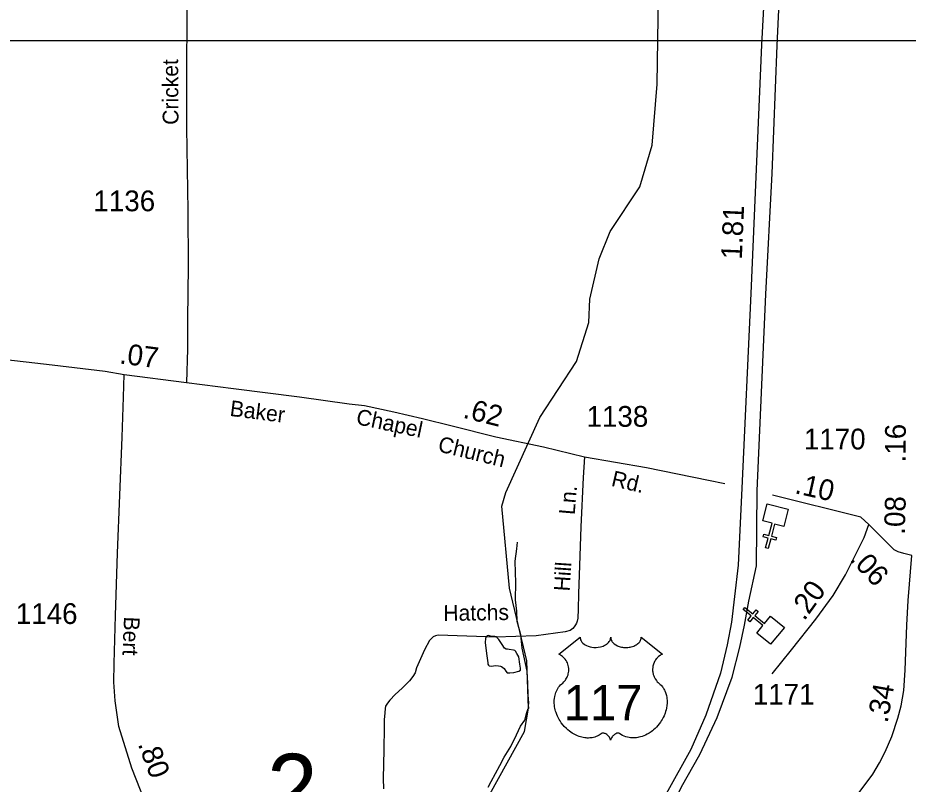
# Model space of a CAD drawing. Extents: x 2206922 to 2357709, y 510027 to 673830.
# Drawn here: x 2276310 to 2281670, y 535777 to 540388 of the extents above; entities that cross this region are included whole.
import ezdxf

# ---------------------------------------------------------------- set-up
doc = ezdxf.new("R2010")
doc.units = 0
for name, color, linetype in [('Exist Cultural Church CELL', 7, 'Continuous'), ('Exist Hydrographic Creek Single Shore', 7, 'Continuous'), ('Exist Hydrographic Misc Water Feature', 7, 'Continuous'), ('Exist Road Non-System Type 51', 7, 'Continuous'), ('Exist Road Non-System Type 51 Label', 7, 'Continuous'), ('Exist Road Primary US Attributed', 7, 'Continuous'), ('Exist Road Primary US Divided Attributed', 7, 'Continuous'), ('Exist Road Primary US Mileage Hundredths English Label', 7, 'Continuous'), ('Exist Road Primary US Shield CELL', 7, 'Continuous'), ('Exist Road Primary US Shield Number Label', 7, 'Continuous'), ('Exist Road Secondary Mileage Hundredths English Label', 7, 'Continuous'), ('Exist Road Secondary Structure Standard Bridge Number Label', 7, 'Continuous'), ('Exist Road Secondary Type 51 Attributed', 7, 'Continuous'), ('Exist Road Secondary Type 51 Label', 7, 'Continuous'), ('Exist Road Secondary Type 51 Number Label', 7, 'Continuous'), ('Map Preparation Inset Cut Line', 7, 'Continuous')]:
    doc.layers.add(name, color=color, linetype=linetype)

msp = doc.modelspace()

# ---------------------------------------------------------------- linework, layer by layer
at = {"layer": 'Exist Cultural Church CELL'}
for points in [[(2280920.6, 537328.1), (2280865.5, 537342.4), (2280846.2, 537268.8), (2280877.1, 537260.7), (2280873.1, 537245.2), (2280842.1, 537253.3), (2280826.8, 537195.2), (2280811.3, 537199.2), (2280826.6, 537257.4), (2280795.7, 537265.5), (2280799.7, 537281), (2280830.7, 537272.8), (2280850, 537346.5), (2280794.3, 537361.2), (2280821.3, 537464.2), (2280947.6, 537431)], [(2280759, 536686.5), (2280795, 536730.7), (2280736.1, 536778.9), (2280715.8, 536754.1), (2280703.4, 536764.2), (2280723.7, 536789), (2280677.2, 536827.1), (2280687.3, 536839.5), (2280733.9, 536801.4), (2280754.1, 536826.2), (2280766.5, 536816.1), (2280746.2, 536791.3), (2280805.1, 536743.1), (2280841.7, 536787.6), (2280924.1, 536720.2), (2280841.4, 536619.1)]]:
    msp.add_lwpolyline(points, close=True, dxfattribs=at)
at = {"layer": 'Exist Hydrographic Creek Single Shore'}
msp.add_lwpolyline([(2278492.8, 534526.4), (2279361, 536093), (2279385, 536233.5), (2279373.9, 536519), (2279270, 536957.3), (2279223.8, 537450.2), (2279247.8, 537531.7), (2279451.8, 537983.5), (2279673.9, 538320.1), (2279746.9, 538554.7), (2279753.9, 538695.6), (2279809.9, 538937.2), (2279874.9, 539103.1), (2280054.9, 539371.7), (2280127.9, 539622.7), (2280157.8, 539989.4), (2280167.9, 540655), (2280164.8, 540669.7)], dxfattribs=at)
at = {"layer": 'Exist Hydrographic Misc Water Feature'}
for points in [[(2279141.6, 535758.8), (2279158.6, 535792.7), (2279212.1, 535889.3), (2279237.6, 535939.4), (2279278.8, 536003.7), (2279312.2, 536074.1), (2279335.4, 536126.6), (2279361.4, 536162.4), (2279367.2, 536184.7), (2279373.1, 536202.8), (2279381.1, 536226.8), (2279386.6, 536234.9), (2279384.4, 536252.6), (2279386.6, 536262.9), (2279384.4, 536292.8), (2279381.7, 536312.6), (2279379.3, 536384.8), (2279376.8, 536456.5), (2279345.6, 536596.3), (2279338.5, 536676), (2279326.4, 536720), (2279316.1, 536756), (2279313.6, 536817.6), (2279306.7, 536885.6), (2279307.9, 536989.6), (2279305, 537049.7), (2279304.4, 537119.5), (2279313.6, 537193.5), (2279317.3, 537233.5)], [(2279325.9, 536544.1), (2279313.4, 536563.8), (2279305.6, 536578), (2279301.1, 536581.9), (2279293.3, 536583.9), (2279267.3, 536587.4), (2279257.3, 536589.3), (2279249.3, 536589.3), (2279239.6, 536595.2), (2279225.1, 536617.3), (2279204.8, 536646.7), (2279192.9, 536658.6), (2279190.8, 536662.6), (2279181, 536666.5), (2279154.9, 536668.4), (2279142.8, 536672.3), (2279134.8, 536670.2), (2279129.1, 536664.2), (2279125, 536654.3), (2279122.9, 536630.2), (2279131.6, 536564), (2279138.5, 536506.2), (2279140.2, 536498.3), (2279144.3, 536492.4), (2279148.4, 536488.5), (2279162.3, 536486.4), (2279172.6, 536488.5), (2279188.1, 536490.6), (2279204.6, 536489), (2279216.4, 536487.2), (2279222.6, 536485), (2279230.6, 536479.4), (2279238.4, 536473.3), (2279248.6, 536457.6), (2279255, 536447.3), (2279272.8, 536447.5), (2279296.6, 536447.9), (2279326.6, 536456), (2279336.4, 536462.2), (2279336.4, 536474.4), (2279332.3, 536498.1), (2279325.9, 536544.1)]]:
    msp.add_lwpolyline(points, dxfattribs=at)
at = {"layer": 'Exist Road Non-System Type 51'}
msp.add_lwpolyline([(2279720.4, 537746.7), (2279713.9, 537623.2), (2279698.3, 537325.6), (2279690.5, 537092.9), (2279685.4, 536921.5), (2279682.8, 536830.5), (2279680.2, 536775.9), (2279677.6, 536758.6), (2279672.4, 536746), (2279667.6, 536735.6), (2279659.4, 536723.9), (2279650.7, 536713.3), (2279634.7, 536701.8), (2279604.1, 536694.4), (2279429.5, 536669.3), (2279185.3, 536661.5), (2278841.3, 536673), (2278825.4, 536670.4), (2278810.2, 536662.8), (2278788.6, 536640.6), (2278758.8, 536585), (2278711, 536477.1), (2278701.3, 536446.4), (2278689, 536425.2), (2278667.9, 536397.9), (2278624.7, 536355.6), (2278582.4, 536315.9), (2278548.9, 536282.4), (2278535.7, 536264.7), (2278524.2, 536247.1), (2278521.6, 536233), (2278518.9, 536205.7), (2278515.4, 536163.3), (2278516.3, 536120.1), (2278513.6, 535982.6), (2278509.2, 535811.5), (2278511, 535748.9)], dxfattribs=at)
at = {"layer": 'Exist Road Primary US Attributed'}
msp.add_lwpolyline([(2281196.6, 535499.5), (2281261.8, 535584.6), (2281356.7, 535703), (2281455.9, 535837.9), (2281496.6, 535905.3), (2281530.9, 535971.4), (2281570.3, 536064.3), (2281607.2, 536174.9), (2281627.4, 536247.6), (2281644, 536341.5), (2281650.4, 536462.3), (2281660.6, 536734.5), (2281668.5, 536883.1), (2281691.1, 537152.6)], dxfattribs=at)
at = {"layer": 'Exist Road Primary US Divided Attributed'}
for points in [[(2281123.2, 543168.4), (2280963.1, 542286.2), (2280889.6, 541750.5), (2280839.6, 541200), (2280786.6, 540225.7), (2280721.9, 538730.5), (2280668.9, 537559), (2280645.4, 537093.9), (2280624.8, 536905.5), (2280605.1, 536752.5), (2280579, 536616.1), (2280539, 536445.7), (2280451.7, 536191.7), (2280360.9, 535984.7), (2280213.6, 535718), (2280172.2, 535655.7), (2279502, 534810.1)], [(2279430.3, 534652.5), (2279800, 535100.2), (2280271.8, 535691.3), (2280304.5, 535759.9), (2280414.7, 535956.4), (2280518.9, 536179), (2280609.1, 536421.6), (2280657.2, 536602.1), (2280683.3, 536734.5), (2280710.1, 536879), (2280755.9, 537091), (2280761.4, 537542.5), (2280813.1, 538724.6), (2280851.3, 539451.6), (2280880.8, 540222.8), (2280924.9, 541173.5), (2280974.9, 541724), (2281042.5, 542200.8), (2281205.4, 543126.5)]]:
    msp.add_lwpolyline(points, dxfattribs=at)
at = {"layer": 'Exist Road Primary US Shield CELL'}
msp.add_lwpolyline([(2279694.8, 536660.8), (2279695.2, 536655.5), (2279696.5, 536649.2), (2279697.4, 536645.9), (2279700.4, 536639.7), (2279705.3, 536632.3), (2279712.1, 536625.1), (2279719.7, 536618.8), (2279724.9, 536615.5), (2279733.7, 536610.7), (2279743.6, 536606.6), (2279754.7, 536603.4), (2279766, 536601.1), (2279778.4, 536599.7), (2279790.6, 536599.5), (2279803.8, 536600.5), (2279818.4, 536603.3), (2279825.2, 536605), (2279832.7, 536607.6), (2279839.7, 536610.5), (2279847.4, 536614.6), (2279853.5, 536618.6), (2279858.3, 536622.1), (2279865.2, 536628.6), (2279870.6, 536635.4), (2279872.9, 536639.2), (2279874.9, 536642.8), (2279877.6, 536650.6), (2279878.3, 536654), (2279878.9, 536661.1), (2279879.3, 536655.1), (2279879.9, 536651.4), (2279880.9, 536647.8), (2279882.4, 536643.9), (2279885.1, 536638.4), (2279888.2, 536633.8), (2279893.9, 536627.1), (2279897.5, 536623.7), (2279900.8, 536621.1), (2279909.5, 536615.1), (2279919.7, 536609.9), (2279924.7, 536607.7), (2279929.9, 536605.9), (2279936.4, 536603.9), (2279943.2, 536602.3), (2279949.9, 536601.2), (2279956.7, 536600.2), (2279963.7, 536599.6), (2279969.4, 536599.5), (2279976.4, 536599.6), (2279982.8, 536600), (2279989.4, 536600.7), (2279996.7, 536601.9), (2280002.6, 536603.2), (2280010.3, 536605.3), (2280017.3, 536607.8), (2280023.4, 536610.4), (2280031.4, 536614.6), (2280037.9, 536618.6), (2280042.6, 536622.4), (2280048.2, 536627.6), (2280053.5, 536633.8), (2280056.6, 536638.3), (2280058.8, 536642.9), (2280060.9, 536647.8), (2280062.1, 536652.9), (2280062.8, 536657.4), (2280062.9, 536661.2), (2280191.5, 536558.8), (2280188.4, 536557.6), (2280181.5, 536554.2), (2280175.9, 536550.9), (2280167.1, 536544.7), (2280163.3, 536541.3), (2280159.5, 536537.7), (2280156, 536533.9), (2280152.9, 536530.3), (2280149.2, 536525.2), (2280145.8, 536520), (2280142.6, 536514.3), (2280140.2, 536509.4), (2280136.2, 536499), (2280134.3, 536492.5), (2280133.1, 536487), (2280131.6, 536475.5), (2280131.2, 536470), (2280131.2, 536464.6), (2280131.5, 536458.9), (2280132.1, 536453.4), (2280133, 536447.8), (2280134, 536442.7), (2280135.5, 536436.6), (2280137.8, 536429.4), (2280140.6, 536422.5), (2280146.5, 536411.4), (2280154.1, 536400), (2280159.5, 536393.6), (2280164.8, 536388.1), (2280172.7, 536381.4), (2280177, 536377.6), (2280181.9, 536372.7), (2280190, 536363.3), (2280193.3, 536358.9), (2280196.6, 536354), (2280199.6, 536348.9), (2280202.6, 536343.4), (2280205.1, 536338.6), (2280209.6, 536327.6), (2280212.9, 536316.9), (2280214.4, 536311.3), (2280216.8, 536298.7), (2280217.7, 536292.4), (2280218.7, 536280.1), (2280218.7, 536265.2), (2280217.6, 536251.1), (2280214.9, 536234.6), (2280212.7, 536224.7), (2280209.4, 536213.3), (2280206.1, 536203.3), (2280200.2, 536188.6), (2280195, 536178), (2280188.3, 536165.5), (2280183.6, 536158), (2280178.2, 536150), (2280171.5, 536140.7), (2280163.6, 536130.8), (2280154.1, 536120.4), (2280146.4, 536112.7), (2280136.4, 536103.8), (2280130.3, 536098.7), (2280121.6, 536092.2), (2280109.8, 536084.3), (2280098.1, 536077.5), (2280088.2, 536072.5), (2280079.3, 536068.7), (2280068, 536064.3), (2280049, 536059.1), (2280042.1, 536057.6), (2280033.9, 536056.4), (2280026.2, 536055.7), (2280018.7, 536055.2), (2280008.7, 536055.2), (2279998.8, 536056), (2279989.4, 536057.3), (2279979.6, 536059.4), (2279969.3, 536062.4), (2279960, 536066.1), (2279950.6, 536070.7), (2279934.7, 536080.7), (2279930.1, 536083.2), (2279927.5, 536083.8), (2279921.3, 536084.2), (2279915.6, 536082.9), (2279909.6, 536080.6), (2279906.1, 536078.7), (2279901.3, 536075.6), (2279897.7, 536072.7), (2279893.3, 536068.5), (2279890.2, 536065), (2279887.9, 536062.3), (2279883.4, 536055.2), (2279881.8, 536051.9), (2279880.2, 536047.5), (2279878.7, 536041.2), (2279876.7, 536049.2), (2279874.3, 536054.5), (2279871.6, 536059.1), (2279868.7, 536063.1), (2279864.3, 536068.3), (2279860.2, 536072.1), (2279855.4, 536076.1), (2279850.2, 536079.2), (2279846.1, 536081.3), (2279842.3, 536082.8), (2279837.6, 536083.9), (2279833.8, 536084.2), (2279830.7, 536084.2), (2279826.4, 536083.2), (2279820.6, 536079), (2279815.1, 536075.2), (2279809.1, 536071.5), (2279802, 536067.7), (2279796.7, 536065.2), (2279790.5, 536062.8), (2279783.2, 536060.4), (2279775.3, 536058.3), (2279767.2, 536056.7), (2279760.1, 536055.6), (2279752.4, 536054.9), (2279745.5, 536054.7), (2279738.3, 536054.7), (2279731.5, 536055.3), (2279723.7, 536056), (2279714, 536057.4), (2279705.9, 536059.2), (2279697.4, 536061.5), (2279688.7, 536064.2), (2279679.3, 536067.8), (2279667.6, 536072.9), (2279659.5, 536077.1), (2279646.7, 536084.5), (2279631.6, 536094.9), (2279620.3, 536104.1), (2279612, 536111.6), (2279599.7, 536124), (2279592.6, 536132.2), (2279581.3, 536146.8), (2279574.1, 536157.3), (2279569.4, 536165.1), (2279562.6, 536177.5), (2279558.8, 536185.4), (2279553.9, 536196.8), (2279550.1, 536207.2), (2279546.9, 536217.1), (2279545.2, 536223.4), (2279542.8, 536234.4), (2279541.3, 536242.2), (2279539.9, 536252.9), (2279539.1, 536264.2), (2279538.9, 536274.6), (2279539.2, 536283.3), (2279540.2, 536293.4), (2279541.9, 536304.1), (2279543.9, 536313.3), (2279545.8, 536319.9), (2279548.5, 536328), (2279552.1, 536336.9), (2279556.4, 536345.4), (2279560.4, 536352.5), (2279565.5, 536360.1), (2279570.5, 536366.5), (2279577.1, 536373.7), (2279583.9, 536380.2), (2279590.2, 536385.3), (2279597.7, 536392.6), (2279601.5, 536397), (2279606.2, 536403.1), (2279609.9, 536408.8), (2279612.9, 536413.9), (2279616.8, 536421.5), (2279619.2, 536427.1), (2279622.1, 536435.7), (2279623.6, 536441.8), (2279625.1, 536449.6), (2279626.1, 536457), (2279626.5, 536466.2), (2279626.3, 536473.8), (2279625.3, 536482.7), (2279623.6, 536491.2), (2279621.6, 536498.7), (2279618.4, 536507.2), (2279615.5, 536513.4), (2279610.5, 536521.8), (2279605.1, 536529.7), (2279599.4, 536536), (2279593.7, 536541.7), (2279588.2, 536546), (2279583, 536549.7), (2279576.5, 536553.7), (2279570.2, 536556.8), (2279566.2, 536558.4)], close=True, dxfattribs=at)
at = {"layer": 'Exist Road Secondary Type 51 Attributed'}
msp.add_line((2276951.3, 538241.8), (2277325.4, 538193.7), dxfattribs=at)
for points in [[(2277434.5, 542507.5), (2277398.4, 541906.7), (2277372.7, 541444.8), (2277346.2, 541080.7), (2277330.4, 540632.8), (2277326.8, 540252.9), (2277326.4, 540215), (2277325, 539727.2), (2277333.5, 539229.7), (2277334.8, 538895.8), (2277331.8, 538574), (2277331.5, 538394), (2277325.4, 538193.7)], [(2273575.6, 539211.3), (2273704.2, 539160.6), (2273969.2, 539060.5), (2274130.7, 538999.5), (2274199.1, 538973.6), (2274378.3, 538905.9), (2275190.1, 538600.5), (2275466.7, 538499.1), (2275649.9, 538452.3), (2275812.2, 538413.4), (2276010.9, 538367.9), (2276185, 538339.3), (2276517.5, 538300.3), (2276837, 538262.6), (2276951.3, 538241.8)], [(2277838.4, 533706.4), (2277802, 533803.8), (2277650.3, 534218.8), (2277461.7, 534691.4), (2277261.7, 535200.8), (2277127.7, 535541.4), (2276996.8, 535874), (2276918.8, 536124.8), (2276895.5, 536279.1), (2276888.6, 536391), (2276889.4, 536502.9), (2276898.7, 536792.8), (2276911.2, 537166.8), (2276938.3, 537864.9), (2276946.1, 538105.4), (2276951.3, 538241.8)], [(2277325.4, 538193.7), (2277608.5, 538158.6), (2278006, 538108), (2278304.7, 538066.4), (2278396.9, 538054.7), (2278573.6, 538018.3), (2278746.3, 537978), (2278924.2, 537933.8), (2279186.6, 537867.5), (2279474.6, 537806.2), (2279720.4, 537746.7), (2280095, 537681.5), (2280467.3, 537606), (2280565, 537586.7)], [(2281432.5, 537340.4), (2281384.3, 537383.6), (2280853.6, 537515.8)], [(2280850.9, 536440.8), (2280967.7, 536585), (2281114.4, 536769), (2281217.3, 536911.4), (2281292.2, 537036), (2281349, 537148.4), (2281404, 537260.9), (2281432.5, 537340.4)], [(2281691.1, 537152.6), (2281643.6, 537164.1), (2281608.7, 537175.8), (2281585.4, 537187.4), (2281568.8, 537202.4), (2281548.9, 537222.3), (2281499, 537273.9), (2281432.5, 537340.4)]]:
    msp.add_lwpolyline(points, dxfattribs=at)
at = {"layer": 'Map Preparation Inset Cut Line'}
for p, q in [((2280748.1, 540252.9), (2280815.9, 540252.9)), ((2280815.9, 540252.9), (2280838.4, 540252.9)), ((2280838.4, 540252.9), (2280860.9, 540252.9)), ((2280860.9, 540252.9), (2280928.8, 540252.9))]:
    msp.add_line(p, q, dxfattribs=at)
msp.add_lwpolyline([(2271763.2, 540252.9), (2282834.5, 540252.9)], dxfattribs=at)

# ---------------------------------------------------------------- texts
at = {"layer": 'Exist Road Non-System Type 51 Label'}
for s, rotation, p in [('Ln.', 85.0853, (2279661.7, 537394.8)), ('Hill', 86.1749, (2279631.8, 536935.2)), ('Hatchs', 0.8988, (2278872, 536758.8))]:
    msp.add_text(s, height=95, rotation=rotation, dxfattribs=at).set_placement(p)
at = {"layer": 'Exist Road Primary US Mileage Hundredths English Label'}
for s, rotation, p in [('1.81', 87.5215, (2280668.1, 538932.5)), ('.16', 89.558, (2281653.9, 537712.4)), ('.08', 88.4231, (2281648.9, 537276.5)), ('.34', 79.9777, (2281545.2, 536141.4))]:
    msp.add_text(s, height=125, rotation=rotation, dxfattribs=at).set_placement(p)
at = {"layer": 'Exist Road Primary US Shield Number Label'}
msp.add_text('117', height=212.5, dxfattribs=at).set_placement((2279596, 536161.5))
at = {"layer": 'Exist Road Secondary Mileage Hundredths English Label'}
for s, rotation, p in [('.07', 352.6751, (2276918.3, 538309.1)), ('.62', 345.8227, (2278984.4, 537983.1)), ('.10', 347.3607, (2280981.6, 537528.6)), ('.06', 313.1368, (2281313.2, 537127.2)), ('.20', 54.1363, (2281043.6, 536755.2)), ('.80', 290.5111, (2277031.6, 536018.9))]:
    msp.add_text(s, height=125, rotation=rotation, dxfattribs=at).set_placement(p)
at = {"layer": 'Exist Road Secondary Structure Standard Bridge Number Label'}
msp.add_text('2', height=410.1, dxfattribs=at).set_placement((2277810.1, 535549.4))
at = {"layer": 'Exist Road Secondary Type 51 Label'}
for s, rotation, p in [('Cricket', 90.3881, (2277277.7, 539744.8)), ('Baker', 352.7473, (2277582.8, 537993.4)), ('Chapel', 347.9817, (2278341.4, 537944.5)), ('Church', 346.1413, (2278833.4, 537780.7)), ('Rd.', 346.9157, (2279877.4, 537572.6)), ('Bert', 267.5774, (2276949.9, 536786.7))]:
    msp.add_text(s, height=95, rotation=rotation, dxfattribs=at).set_placement(p)
at = {"layer": 'Exist Road Secondary Type 51 Number Label'}
for s, p in [('1136', (2276765.3, 539224.4)), ('1138', (2279733.3, 537927.5)), ('1170', (2281041.4, 537791.1)), ('1146', (2276298.1, 536740.8)), ('1171', (2280734.3, 536255.4))]:
    msp.add_text(s, height=125, dxfattribs=at).set_placement(p)

doc.saveas('drawing.dxf')
